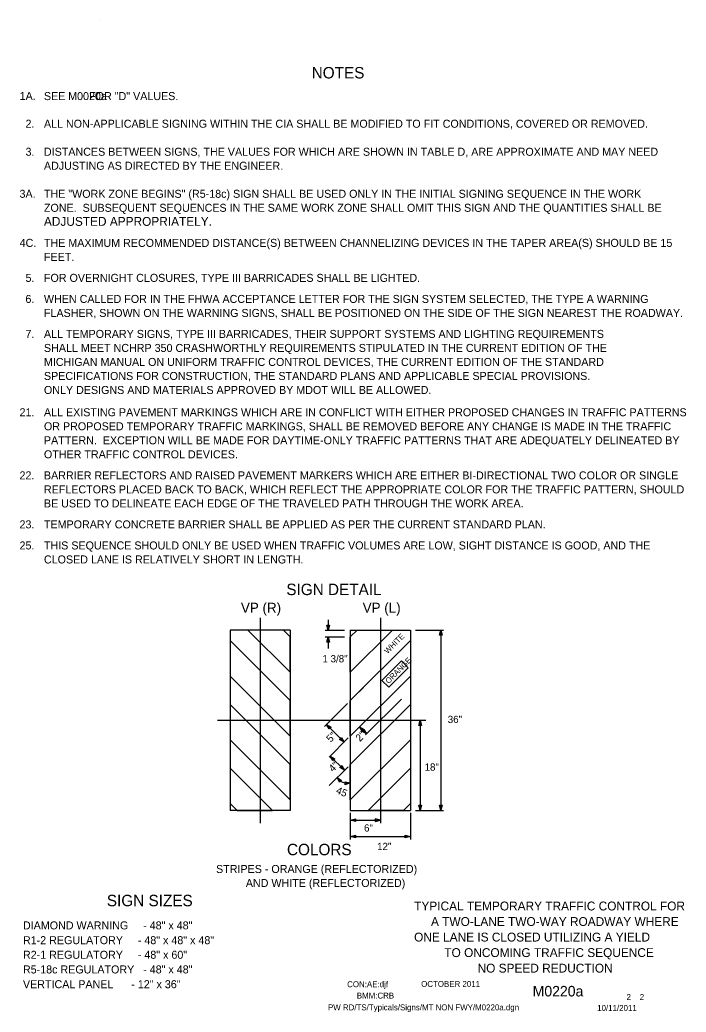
# Model space of a CAD drawing. Extents: x 16784 to 18475, y 7218 to 8259.
# Drawn here: x 17776 to 18475, y 7218 to 8259 of the extents above; entities that cross this region are included whole.
import ezdxf

# ---------------------------------------------------------------- set-up
doc = ezdxf.new("R2010")
doc.units = 0
for name, color, linetype in [('BORDER', 7, 'Continuous'), ('BORDER_SIGNAL_WO', 7, 'Continuous'), ('TRAFFIC_SIGNS_PR', 7, 'Continuous'), ('TYPICAL_TEXT_DIMEN_PR', 7, 'Continuous')]:
    doc.layers.add(name, color=color, linetype=linetype)

msp = doc.modelspace()

# ---------------------------------------------------------------- linework, layer by layer
at = {"layer": 'BORDER'}
msp.add_line((17859.8, 8259.1), (17859.8, 8259.1), dxfattribs=at)
at = {"layer": 'TRAFFIC_SIGNS_PR'}
for p, q in [((18059.9, 7618.8), (17996.9, 7618.8)), ((17996.9, 7618.8), (17996.9, 7429.8)), ((18059.9, 7574.6), (18015.7, 7618.8)), ((18059.9, 7611.7), (18052.8, 7618.8)), ((18059.9, 7618.8), (18059.9, 7429.8)), ((18123, 7618.8), (18186, 7618.8)), ((18123, 7618.8), (18123, 7429.8)), ((18123, 7611.7), (18130.1, 7618.8)), ((18123, 7574.6), (18167.2, 7618.8)), ((18186, 7618.8), (18186, 7429.8)), ((18059.9, 7544.9), (17996.9, 7607.9)), ((18123, 7544.9), (18186, 7607.9)), ((18059.9, 7507.7), (17996.9, 7570.7)), ((18123, 7507.7), (18186, 7570.7)), ((18132.3, 7554.1), (18141.5, 7563.4)), ((18059.9, 7478), (17996.9, 7541)), ((18123, 7478), (18186, 7541)), ((18059.9, 7440.9), (17996.9, 7503.9)), ((18123, 7440.9), (18186, 7503.9)), ((18041.3, 7429.8), (17996.9, 7474.2)), ((18141.6, 7429.8), (18186, 7474.2)), ((18004.2, 7429.8), (17996.9, 7437.1)), ((18178.7, 7429.8), (18186, 7437.1)), ((18059.9, 7429.8), (17996.9, 7429.8)), ((18123, 7429.8), (18186, 7429.8))]:
    msp.add_line(p, q, dxfattribs=at)
for points in [[(18052.8, 7618.8), (18015.7, 7618.8), (18059.9, 7574.6), (18059.9, 7611.7)], [(18130.1, 7618.8), (18167.2, 7618.8), (18123, 7574.6), (18123, 7611.7)], [(18059.9, 7544.9), (17996.9, 7607.9), (17996.9, 7570.7), (18059.9, 7507.7)], [(18123, 7544.9), (18186, 7607.9), (18186, 7570.7), (18123, 7507.7)], [(18059.9, 7478), (17996.9, 7541), (17996.9, 7503.9), (18059.9, 7440.9)], [(18123, 7478), (18186, 7541), (18186, 7503.9), (18123, 7440.9)], [(17996.9, 7474.2), (17996.9, 7437.1), (18004.2, 7429.8), (18041.3, 7429.8)], [(18186, 7474.2), (18186, 7437.1), (18178.7, 7429.8), (18141.6, 7429.8)]]:
    msp.add_lwpolyline(points, close=True, dxfattribs=at)
at = {"layer": 'TYPICAL_TEXT_DIMEN_PR'}
for p, q in [((18028.4, 7631.9), (18028.4, 7416.4)), ((18154.5, 7631.9), (18154.5, 7416.4)), ((18099.9, 7618.8), (18098.4, 7624.2)), ((18098.4, 7624.2), (18099.9, 7624.2)), ((18099.9, 7629.7), (18099.9, 7618.8)), ((18099.9, 7624.2), (18101.3, 7624.2)), ((18101.3, 7624.2), (18099.9, 7618.8)), ((18096.7, 7618.8), (18116.9, 7618.8)), ((18096.7, 7611.7), (18116.9, 7611.7)), ((18098.4, 7606.3), (18099.9, 7611.7)), ((18099.9, 7611.7), (18099.9, 7599.6)), ((18099.9, 7611.7), (18101.3, 7606.3)), ((18191.3, 7618.8), (18220.8, 7618.8)), ((18216.4, 7613.4), (18217.8, 7618.8)), ((18217.8, 7613.4), (18216.4, 7613.4)), ((18217.8, 7618.8), (18217.8, 7429.8)), ((18217.8, 7618.8), (18219.3, 7613.4)), ((18219.3, 7613.4), (18217.8, 7613.4)), ((18099.9, 7606.3), (18098.4, 7606.3)), ((18101.3, 7606.3), (18099.9, 7606.3)), ((18095.9, 7517.7), (18120, 7541.9)), ((18139, 7508.9), (18176.7, 7546.6)), ((17983.8, 7524.3), (18202.2, 7524.3)), ((18116.7, 7501.4), (18098.1, 7520)), ((18100.9, 7515.2), (18098.1, 7520)), ((18098.1, 7520), (18102.9, 7517.2)), ((18101.9, 7516.2), (18100.9, 7515.2)), ((18102.9, 7517.2), (18101.9, 7516.2)), ((18140.1, 7509.9), (18132.6, 7517.4)), ((18135.4, 7512.5), (18132.6, 7517.4)), ((18132.6, 7517.4), (18137.4, 7514.6)), ((18194.7, 7518.9), (18196.2, 7524.3)), ((18196.2, 7518.9), (18194.7, 7518.9)), ((18196.2, 7524.3), (18196.2, 7429.8)), ((18196.2, 7524.3), (18197.6, 7518.9)), ((18197.6, 7518.9), (18196.2, 7518.9)), ((18100.7, 7485.5), (18120.9, 7505.7)), ((18112.9, 7505.2), (18113.9, 7506.3)), ((18113.9, 7506.3), (18116.7, 7501.4)), ((18135.2, 7512.7), (18136.2, 7513.7)), ((18140.1, 7509.9), (18135.2, 7512.7)), ((18136.4, 7513.5), (18135.4, 7512.5)), ((18136.2, 7513.7), (18137.3, 7514.7)), ((18137.4, 7514.6), (18136.4, 7513.5)), ((18137.3, 7514.7), (18140.1, 7509.9)), ((18111.8, 7504.2), (18112.9, 7505.2)), ((18116.7, 7501.4), (18111.8, 7504.2)), ((18116.9, 7471.9), (18102, 7486.8)), ((18104.8, 7482), (18102, 7486.8)), ((18102, 7486.8), (18106.9, 7484)), ((18100.7, 7455.8), (18120.6, 7475.6)), ((18105.8, 7483), (18104.8, 7482)), ((18106.9, 7484), (18105.8, 7483)), ((18112, 7474.7), (18113.1, 7475.7)), ((18116.9, 7471.9), (18112, 7474.7)), ((18113.1, 7475.7), (18114.1, 7476.8)), ((18114.1, 7476.8), (18116.9, 7471.9)), ((18111.6, 7459.2), (18109.2, 7464.2)), ((18109.2, 7464.2), (18113.8, 7461.1)), ((18112.7, 7460.1), (18111.6, 7459.2)), ((18113.8, 7461.1), (18112.7, 7460.1)), ((18117.6, 7458.2), (18117.5, 7459.6)), ((18117.5, 7459.6), (18123, 7458.5)), ((18117.7, 7456.7), (18117.6, 7458.2)), ((18123, 7458.5), (18117.7, 7456.7)), ((18196.2, 7429.8), (18194.7, 7435.2)), ((18194.7, 7435.2), (18196.2, 7435.2)), ((18196.2, 7435.2), (18197.6, 7435.2)), ((18197.6, 7435.2), (18196.2, 7429.8)), ((18217.8, 7429.8), (18216.4, 7435.2)), ((18216.4, 7435.2), (18217.8, 7435.2)), ((18217.8, 7435.2), (18219.3, 7435.2)), ((18219.3, 7435.2), (18217.8, 7429.8)), ((18123, 7427.2), (18123, 7399.2)), ((18186, 7427.2), (18186, 7399.2)), ((18191.3, 7429.8), (18220.8, 7429.8)), ((18123, 7419.6), (18128.4, 7421)), ((18123, 7419.6), (18154.5, 7419.6)), ((18128.4, 7418.1), (18123, 7419.6)), ((18128.4, 7421), (18128.4, 7419.6)), ((18128.4, 7419.6), (18128.4, 7418.1)), ((18154.5, 7419.6), (18149.1, 7421)), ((18149.1, 7421), (18149.1, 7419.6)), ((18149.1, 7419.6), (18149.1, 7418.1)), ((18149.1, 7418.1), (18154.5, 7419.6)), ((18123, 7402.4), (18128.4, 7403.8)), ((18123, 7402.4), (18186, 7402.4)), ((18128.4, 7401), (18123, 7402.4)), ((18128.4, 7403.8), (18128.4, 7402.4)), ((18128.4, 7402.4), (18128.4, 7401)), ((18180.6, 7402.4), (18180.6, 7403.8)), ((18180.6, 7403.8), (18186, 7402.4)), ((18186, 7402.4), (18180.6, 7401)), ((18180.6, 7401), (18180.6, 7402.4))]:
    msp.add_line(p, q, dxfattribs=at)
msp.add_lwpolyline([(18156.1, 7566.1), (18176.6, 7586.5), (18183.7, 7579.3), (18163.3, 7558.9)], close=True, dxfattribs=at)
msp.add_arc((18120.2, 7471.4), 13.1, 212.8393, 282.1565, dxfattribs=at)

# ---------------------------------------------------------------- texts
at = {"layer": 'BORDER'}
for s, p in [('TYPICAL TEMPORARY TRAFFIC CONTROL FOR', (18190, 7324.8)), ('A TWO-LANE TWO-WAY ROADWAY WHERE', (18207.6, 7308.5)), ('ONE LANE IS CLOSED UTILIZING A YIELD ', (18189.9, 7292.2)), ('TO ONCOMING TRAFFIC SEQUENCE', (18221.6, 7275.9)), ('NO SPEED REDUCTION', (18256.5, 7259.6))]:
    msp.add_text(s, height=9.3, dxfattribs=at).set_placement(p)
at = {"layer": 'BORDER_SIGNAL_WO'}
for s, height, p in [('CON:AE:djf', 6.2, (18119.7, 7244.3)), ('    OCTOBER 2011    ', 6.2, (18188.1, 7244.6)), ('    M0220a    ', 11, (18297.9, 7234.6)), ('BMM:CRB   ', 6.2, (18129.8, 7232.4)), (' 2    2 ', 6.2, (18410.4, 7230.9)), ('PW RD/TS/Typicals/Signs/MT NON FWY/M0220a.dgn     ', 6.2, (18099.6, 7220)), ('10/11/2011    ', 6.2, (18381.9, 7219.4))]:
    msp.add_text(s, height=height, dxfattribs=at).set_placement(p)
at = {"layer": 'TYPICAL_TEXT_DIMEN_PR'}
for s, height, p in [('NOTES', 12, (18082.5, 8197.6)), ('1A.', 8.4, (17776.2, 8175)), ('SEE        FOR "D" VALUES.', 8.4, (17801.7, 8174.9)), ('M0020a', 8.4, (17827.1, 8174.9)), ('2.', 8.4, (17782.4, 8145.9)), ('ALL NON-APPLICABLE SIGNING WITHIN THE CIA SHALL BE MODIFIED TO FIT CONDITIONS, COVERED OR REMOVED.', 8.4, (17801.7, 8145.9)), ('3.', 8.4, (17782.4, 8116.5)), ('DISTANCES BETWEEN SIGNS, THE VALUES FOR WHICH ARE SHOWN IN TABLE D, ARE APPROXIMATE AND MAY NEED', 8.4, (17801.7, 8116.5)), ('ADJUSTING AS DIRECTED BY THE ENGINEER.', 8.4, (17801.7, 8101.8)), ('3A.', 8.4, (17776.1, 8072.4)), ('THE "WORK ZONE BEGINS" (R5-18c) SIGN SHALL BE USED ONLY IN THE INITIAL SIGNING SEQUENCE IN THE WORK', 8.4, (17801.7, 8072.4)), ('ZONE.  SUBSEQUENT SEQUENCES IN THE SAME WORK ZONE SHALL OMIT THIS SIGN AND THE QUANTITIES SHALL BE', 8.4, (17801.7, 8057.7)), ('ADJUSTED APPROPRIATELY.', 9.3, (17801.7, 8043)), ('4C.', 8.4, (17776.2, 8020.9)), ('THE MAXIMUM RECOMMENDED DISTANCE(S) BETWEEN CHANNELIZING DEVICES IN THE TAPER AREA(S) SHOULD BE 15', 8.4, (17801.7, 8020.9)), ('FEET.', 8.4, (17801.7, 8006.2)), ('5.', 8.4, (17782.4, 7984.2)), ('FOR OVERNIGHT CLOSURES, TYPE III BARRICADES SHALL BE LIGHTED.', 8.4, (17801.7, 7984.2)), ('6.', 8.4, (17782.3, 7962.1)), ('WHEN CALLED FOR IN THE FHWA ACCEPTANCE LETTER FOR THE SIGN SYSTEM SELECTED, THE TYPE A WARNING ', 8.4, (17801.7, 7962.1)), ('FLASHER, SHOWN ON THE WARNING SIGNS, SHALL BE POSITIONED ON THE SIDE OF THE SIGN NEAREST THE ROADWAY.', 8.4, (17801.7, 7947.4)), ('7.', 8.4, (17782.3, 7925.4)), ('ALL TEMPORARY SIGNS, TYPE III BARRICADES, THEIR SUPPORT SYSTEMS AND LIGHTING REQUIREMENTS', 8.4, (17801.7, 7925.4)), ('SHALL MEET NCHRP 350 CRASHWORTHLY REQUIREMENTS STIPULATED IN THE CURRENT EDITION OF THE', 8.4, (17801.7, 7910.7)), ('MICHIGAN MANUAL ON UNIFORM TRAFFIC CONTROL DEVICES, THE CURRENT EDITION OF THE STANDARD', 8.4, (17801.7, 7896)), ('SPECIFICATIONS FOR CONSTRUCTION, THE STANDARD PLANS AND APPLICABLE SPECIAL PROVISIONS.', 8.4, (17801.7, 7881.3)), ('ONLY DESIGNS AND MATERIALS APPROVED BY MDOT WILL BE ALLOWED.', 8.4, (17801.7, 7866.6)), ('21.', 8.4, (17776.1, 7843.2)), ('ALL EXISTING PAVEMENT MARKINGS WHICH ARE IN CONFLICT WITH EITHER PROPOSED CHANGES IN TRAFFIC PATTERNS', 8.4, (17801.7, 7843.2)), ('OR PROPOSED TEMPORARY TRAFFIC MARKINGS, SHALL BE REMOVED BEFORE ANY CHANGE IS MADE IN THE TRAFFIC', 8.4, (17801.7, 7828.5)), ('PATTERN.  EXCEPTION WILL BE MADE FOR DAYTIME-ONLY TRAFFIC PATTERNS THAT ARE ADEQUATELY DELINEATED BY', 8.4, (17801.7, 7813.8)), ('OTHER TRAFFIC CONTROL DEVICES.', 8.4, (17801.7, 7799.1)), ('22.', 8.4, (17776.1, 7777)), ('BARRIER REFLECTORS AND RAISED PAVEMENT MARKERS WHICH ARE EITHER BI-DIRECTIONAL TWO COLOR OR SINGLE', 8.4, (17801.7, 7777)), ('REFLECTORS PLACED BACK TO BACK, WHICH REFLECT THE APPROPRIATE COLOR FOR THE TRAFFIC PATTERN, SHOULD', 8.4, (17801.7, 7762.3)), ('BE USED TO DELINEATE EACH EDGE OF THE TRAVELED PATH THROUGH THE WORK AREA.', 8.4, (17801.7, 7747.6)), ('23.', 8.4, (17776.1, 7725.6)), ('TEMPORARY CONCRETE BARRIER SHALL BE APPLIED AS PER THE CURRENT STANDARD PLAN.', 8.4, (17801.7, 7725.6)), ('25.', 8.4, (17776.1, 7703.5)), ('THIS SEQUENCE SHOULD ONLY BE USED WHEN TRAFFIC VOLUMES ARE LOW, SIGHT DISTANCE IS GOOD, AND THE', 8.4, (17801.7, 7703.5)), ('CLOSED LANE IS RELATIVELY SHORT IN LENGTH.', 8.4, (17801.7, 7688.8)), ('SIGN DETAIL', 12, (18055.9, 7655.6)), ('VP (R)', 10.5, (18008.3, 7637.1)), ('VP (L)', 10.5, (18136, 7637.1)), ('1 3/8"', 7.65, (18093.8, 7585)), ('36"', 7.65, (18225.2, 7521.4)), ('18"', 7.65, (18200.9, 7471.4)), ('6"', 7.65, (18137.4, 7407.5)), ('COLORS', 12, (18056.6, 7382.7)), ('12"', 7.65, (18151.1, 7388.1)), ('STRIPES - ORANGE (REFLECTORIZED)', 8.4, (17982.2, 7364.1)), ('          AND WHITE (REFLECTORIZED)', 8.4, (17982.2, 7349.4)), ('SIGN SIZES', 12, (17867.7, 7329.2)), ('DIAMOND WARNING     - 48" x 48"', 8.4, (17779.7, 7304.9)), ('R1-2 REGULATORY     - 48" x 48" x 48"', 8.4, (17779.7, 7289.4)), ('R2-1 REGULATORY     - 48" x 60"', 8.4, (17779.7, 7274.1)), ('R5-18c REGULATORY   - 48" x 48"', 8.4, (17779.7, 7258.7)), ('VERTICAL PANEL      - 12" x 36"', 8.4, (17779.7, 7243.2))]:
    msp.add_text(s, height=height, dxfattribs=at).set_placement(p)
for s, height, rotation, p in [('WHITE', 6, 45, (18162.2, 7593.5)), ('ORANGE', 6, 45, (18163.2, 7562.1)), ('5"', 7.65, 45, (18102.4, 7500.6)), ('2"', 7.65, 45.0095, (18133.1, 7501.4)), ('4"', 7.65, 45, (18104.8, 7469.5)), ('45', 7.65, 337.5007, (18107.3, 7447.9))]:
    msp.add_text(s, height=height, rotation=rotation, dxfattribs=at).set_placement(p)

doc.saveas('drawing.dxf')
